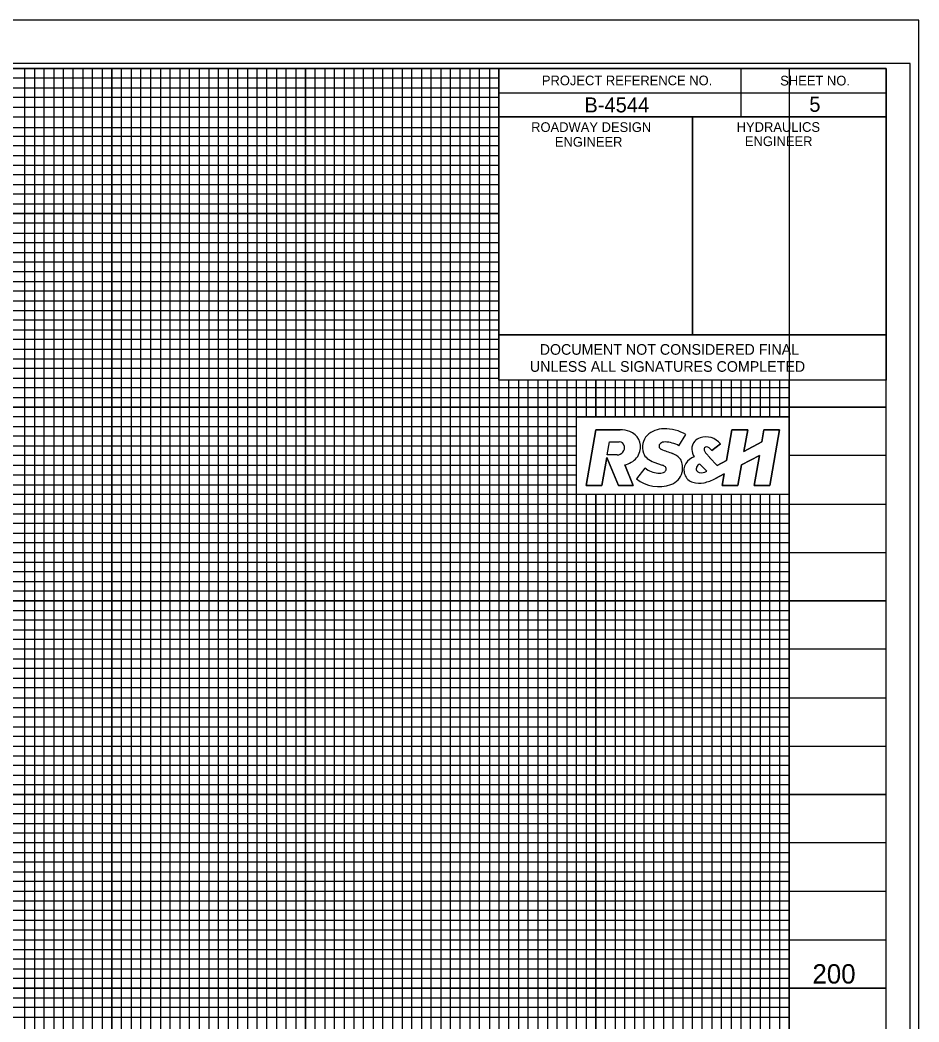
# Model space of a CAD drawing. Extents: x 1728093 to 1729777, y 538013 to 539113.
# Drawn here: x 1729312 to 1729777, y 538595 to 539113 of the extents above; entities that cross this region are included whole.
import ezdxf

# ---------------------------------------------------------------- set-up
doc = ezdxf.new("R2010")
doc.units = 0
for name, color, linetype in [('Exist Vertical Profile Vertical Axis Label', 7, 'Continuous'), ('Prop DSN Text', 7, 'Continuous'), ('Scratch_Level_0', 7, 'Continuous'), ('Sheet Cutting Line CELL', 7, 'Continuous'), ('Sheet Data Field CELL', 7, 'Continuous'), ('Sheet DOT Grid CELL', 7, 'Continuous'), ('Sheet Plot Border Inside CELL', 7, 'Continuous'), ('Sheet Plot Border Outside CELL', 7, 'Continuous'), ('Sheet Profile CELL', 7, 'Continuous'), ('Sheet Profile Grid Major CELL', 7, 'Continuous'), ('Sheet Profile Grid Middle CELL', 7, 'Continuous'), ('Sheet Profile Grid Minor CELL', 7, 'Continuous'), ('Sheet Sticker Exception Certification CELL', 7, 'Continuous'), ('Sheet Sticker Incomplete CELL', 7, 'Continuous')]:
    doc.layers.add(name, color=color, linetype=linetype)

msp = doc.modelspace()

# ---------------------------------------------------------------- linework, layer by layer
at = {"layer": 'Prop DSN Text'}
for p, q in [((1729599.88, 538907.97), (1729709.89, 538907.99)), ((1729599.88, 538867.97), (1729599.88, 538907.97)), ((1729709.89, 538907.99), (1729709.9, 538867.99)), ((1729709.9, 538867.99), (1729599.88, 538867.97))]:
    msp.add_line(p, q, dxfattribs=at)
at = {"layer": 'Scratch_Level_0'}
msp.add_lwpolyline([(1728309.89, 539087.97), (1729709.89, 539087.97), (1729709.89, 538062.97), (1728309.89, 538062.97)], close=True, dxfattribs=at)
at = {"layer": 'Sheet Cutting Line CELL'}
msp.add_line((1729776.89, 539112.97), (1728092.89, 539112.97), dxfattribs=at)
at = {"layer": 'Sheet DOT Grid CELL'}
for p, q in [((1729359.89, 539087.97), (1729359.89, 538062.97)), ((1729409.89, 539087.97), (1729409.89, 538062.97)), ((1729459.89, 539087.97), (1729459.89, 538062.97)), ((1729509.89, 539087.97), (1729509.89, 538062.97)), ((1728259.89, 539062.97), (1729559.84, 539062.97)), ((1728259.89, 539012.97), (1729559.84, 539012.97)), ((1728259.89, 538962.97), (1729559.84, 538962.97)), ((1729559.89, 538062.97), (1729559.89, 538950.42)), ((1729609.89, 538907.97), (1729609.89, 538926.92)), ((1729659.89, 538907.98), (1729659.89, 538926.92)), ((1729709.89, 538062.97), (1729709.89, 538926.92)), ((1728259.89, 538912.97), (1729759.89, 538912.97)), ((1729609.89, 538062.97), (1729609.89, 538867.97)), ((1729659.89, 538062.97), (1729659.89, 538867.98)), ((1728259.89, 538862.97), (1729759.89, 538862.97)), ((1728259.89, 538812.97), (1729759.89, 538812.97)), ((1728259.89, 538762.97), (1729759.89, 538762.97)), ((1728259.89, 538712.97), (1729759.89, 538712.97)), ((1728259.89, 538612.97), (1729759.89, 538612.97))]:
    msp.add_line(p, q, dxfattribs=at)
at = {"layer": 'Sheet Plot Border Inside CELL'}
msp.add_lwpolyline([(1729772.39, 539090.52), (1728105.89, 539090.52), (1728105.89, 538035.42), (1729772.39, 538035.42)], close=True, dxfattribs=at)
at = {"layer": 'Sheet Plot Border Outside CELL'}
msp.add_lwpolyline([(1729776.89, 539112.97), (1728092.89, 539112.97), (1728092.89, 538012.97), (1729776.89, 538012.97)], close=True, dxfattribs=at)
at = {"layer": 'Sheet Profile CELL'}
for p, q in [((1729684.89, 539087.92), (1729684.89, 539062.92)), ((1729559.84, 539075.42), (1729759.89, 539075.42)), ((1729659.89, 539062.92), (1729659.89, 538950.47))]:
    msp.add_line(p, q, dxfattribs=at)
for points in [[(1729759.89, 539087.97), (1728259.89, 539087.97), (1728259.89, 538037.97), (1729759.89, 538037.97)], [(1729559.84, 539087.97), (1729759.89, 539087.97), (1729759.89, 539062.92), (1729559.84, 539062.92)], [(1729559.84, 539062.92), (1729659.89, 539062.92), (1729659.89, 538950.42), (1729559.84, 538950.42)], [(1729659.89, 539062.92), (1729759.89, 539062.92), (1729759.89, 538950.42), (1729659.89, 538950.42)]]:
    msp.add_lwpolyline(points, close=True, dxfattribs=at)
at = {"layer": 'Sheet Profile Grid Major CELL'}
for points in [[(1729359.89, 538062.97), (1729359.89, 539087.97), (1729409.89, 539087.97), (1729409.89, 538062.97)], [(1729459.89, 538062.97), (1729459.89, 539087.97), (1729509.89, 539087.97), (1729509.89, 538062.97)], [(1729559.89, 538062.97), (1729559.89, 539087.97), (1729586.19, 539087.97)], [(1729559.84, 539012.97), (1728259.99, 539012.97), (1728259.99, 539062.92), (1729559.84, 539062.92)], [(1729759.89, 538912.97), (1728259.89, 538912.97), (1728259.89, 538962.97), (1729559.84, 538962.97)], [(1729609.89, 538926.92), (1729609.89, 538907.97)], [(1729659.89, 538907.98), (1729659.89, 538926.92)], [(1729709.89, 538926.92), (1729709.89, 538062.97), (1729759.89, 538062.97)], [(1729609.89, 538867.97), (1729609.89, 538062.97), (1729659.89, 538062.97), (1729659.89, 538867.98)], [(1729759.89, 538812.97), (1728259.89, 538812.97), (1728259.89, 538862.97), (1729759.89, 538862.97)], [(1729759.89, 538712.97), (1728259.89, 538712.97), (1728259.89, 538762.97), (1729759.89, 538762.97)], [(1729759.89, 538612.97), (1728259.89, 538612.97), (1728259.89, 538662.97), (1729759.89, 538662.97)]]:
    msp.add_lwpolyline(points, dxfattribs=at)
at = {"layer": 'Sheet Profile Grid Middle CELL'}
for points in [[(1729334.89, 538062.97), (1729334.89, 539087.97), (1729384.89, 539087.97), (1729384.89, 538062.97)], [(1729434.89, 538062.97), (1729434.89, 539087.97), (1729484.89, 539087.97), (1729484.89, 538062.97)], [(1729534.89, 538062.97), (1729534.89, 539087.97)], [(1728259.89, 539037.97), (1729559.84, 539037.97)], [(1729559.84, 538987.97), (1728259.89, 538987.97), (1728259.89, 538937.92), (1729559.84, 538937.92)], [(1729584.89, 538926.92), (1729584.89, 538062.97), (1729634.89, 538062.97), (1729634.89, 538867.98)], [(1729634.89, 538907.98), (1729634.89, 538926.92)], [(1729684.89, 538926.92), (1729684.89, 538907.98)], [(1729599.88, 538887.97), (1728259.89, 538887.97), (1728259.89, 538837.97), (1729759.89, 538837.97)], [(1729759.89, 538887.97), (1729709.89, 538887.97)], [(1729684.89, 538867.98), (1729684.89, 538062.97)], [(1729759.89, 538787.97), (1728259.89, 538787.97), (1728259.89, 538737.97), (1729759.89, 538737.97)], [(1729759.89, 538687.97), (1728259.89, 538687.97), (1728259.89, 538637.97), (1729759.89, 538637.97)]]:
    msp.add_lwpolyline(points, dxfattribs=at)
at = {"layer": 'Sheet Profile Grid Minor CELL'}
for p, q in [((1729709.89, 538922.97), (1728309.89, 538922.97)), ((1728309.89, 538917.97), (1729709.89, 538917.97)), ((1729709.89, 538907.97), (1728309.89, 538907.97)), ((1728309.89, 538902.97), (1729599.88, 538902.97)), ((1729599.88, 538882.97), (1728309.89, 538882.97)), ((1729709.89, 538852.97), (1728309.89, 538852.97)), ((1728309.89, 538847.97), (1729709.89, 538847.97))]:
    msp.add_line(p, q, dxfattribs=at)
for points in [[(1729314.89, 538062.97), (1729314.89, 539087.97), (1729319.89, 539087.97), (1729319.89, 538062.97)], [(1729324.89, 538062.97), (1729324.89, 539087.97), (1729329.89, 539087.97), (1729329.89, 538062.97)], [(1729339.89, 538062.97), (1729339.89, 539087.97), (1729344.89, 539087.97), (1729344.89, 538062.97)], [(1729349.89, 538062.97), (1729349.89, 539087.97), (1729354.89, 539087.97), (1729354.89, 538062.97)], [(1729364.89, 538062.97), (1729364.89, 539087.97), (1729369.89, 539087.97), (1729369.89, 538062.97)], [(1729374.89, 538062.97), (1729374.89, 539087.97), (1729379.89, 539087.97), (1729379.89, 538062.97)], [(1729389.89, 538062.97), (1729389.89, 539087.97), (1729394.89, 539087.97), (1729394.89, 538062.97)], [(1729399.89, 538062.97), (1729399.89, 539087.97), (1729404.89, 539087.97), (1729404.89, 538062.97)], [(1729414.89, 538062.97), (1729414.89, 539087.97), (1729419.89, 539087.97), (1729419.89, 538062.97)], [(1729424.89, 538062.97), (1729424.89, 539087.97), (1729429.89, 539087.97), (1729429.89, 538062.97)], [(1729439.89, 538062.97), (1729439.89, 539087.97), (1729444.89, 539087.97), (1729444.89, 538062.97)], [(1729449.89, 538062.97), (1729449.89, 539087.97), (1729454.89, 539087.97), (1729454.89, 538062.97)], [(1729464.89, 538062.97), (1729464.89, 539087.97), (1729469.89, 539087.97), (1729469.89, 538062.97)], [(1729474.89, 538062.97), (1729474.89, 539087.97), (1729479.89, 539087.97), (1729479.89, 538062.97)], [(1729489.89, 538062.97), (1729489.89, 539087.97), (1729494.89, 539087.97), (1729494.89, 538062.97)], [(1729499.89, 538062.97), (1729499.89, 539087.97), (1729504.89, 539087.97), (1729504.89, 538062.97)], [(1729514.89, 538062.97), (1729514.89, 539087.97), (1729519.89, 539087.97), (1729519.89, 538062.97)], [(1729524.89, 538062.97), (1729524.89, 539087.97), (1729529.89, 539087.97), (1729529.89, 538062.97)], [(1729539.89, 538062.97), (1729539.89, 539087.97), (1729544.89, 539087.97), (1729544.89, 538062.97)], [(1729549.89, 538062.97), (1729549.89, 539087.97), (1729554.89, 539087.97), (1729554.89, 538062.97)], [(1729559.84, 539082.97), (1728309.89, 539082.97), (1728309.89, 539077.97), (1729559.84, 539077.97)], [(1729559.84, 539072.97), (1728309.89, 539072.97), (1728309.89, 539067.97), (1729559.84, 539067.97)], [(1729559.84, 539057.22), (1728310.89, 539057.22), (1728310.89, 539052.97), (1729559.84, 539052.97)], [(1729559.84, 539047.97), (1728309.89, 539047.97), (1728309.89, 539042.97), (1729559.84, 539042.97)], [(1729559.84, 539032.97), (1728309.89, 539032.97), (1728309.89, 539027.97), (1729559.84, 539027.97)], [(1729559.84, 539022.97), (1728309.89, 539022.97), (1728309.89, 539017.97), (1729559.84, 539017.97)], [(1729559.84, 539007.97), (1728309.89, 539007.97), (1728309.89, 539002.97), (1729559.84, 539002.97)], [(1729559.84, 538997.97), (1728309.89, 538997.97), (1728309.89, 538992.97), (1729559.84, 538992.97)], [(1729559.84, 538982.97), (1728309.89, 538982.97), (1728309.89, 538977.97), (1729559.84, 538977.97)], [(1729559.84, 538972.97), (1728309.89, 538972.97), (1728309.89, 538967.97), (1729559.84, 538967.97)], [(1729559.84, 538957.97), (1728309.89, 538957.97), (1728309.89, 538952.97), (1729559.84, 538952.97)], [(1729559.84, 538947.97), (1728309.89, 538947.97), (1728309.89, 538947.97), (1728309.89, 538927.97), (1729559.84, 538927.97)], [(1728309.89, 538942.97), (1729559.84, 538942.97)], [(1729559.84, 538932.97), (1728309.89, 538932.97)], [(1729564.89, 538062.97), (1729564.89, 538926.92)], [(1729569.89, 538926.92), (1729569.89, 538062.97), (1729574.89, 538062.97), (1729574.89, 538926.92)], [(1729579.89, 538926.92), (1729579.89, 538062.97), (1729589.89, 538062.97), (1729589.89, 538926.92)], [(1729594.89, 538926.92), (1729594.89, 538062.97), (1729599.89, 538062.97), (1729599.89, 538926.92)], [(1729604.89, 538926.92), (1729604.89, 538907.97)], [(1729614.89, 538907.97), (1729614.89, 538926.92)], [(1729619.89, 538926.92), (1729619.89, 538907.97)], [(1729624.89, 538907.98), (1729624.89, 538926.92)], [(1729629.89, 538926.92), (1729629.89, 538907.98)], [(1729639.89, 538907.98), (1729639.89, 538926.92)], [(1729644.89, 538926.92), (1729644.89, 538907.98)], [(1729649.89, 538907.98), (1729649.89, 538926.92)], [(1729654.89, 538926.92), (1729654.89, 538907.98)], [(1729664.89, 538907.98), (1729664.89, 538926.92)], [(1729669.89, 538926.92), (1729669.89, 538907.98)], [(1729674.89, 538907.98), (1729674.89, 538926.92)], [(1729679.89, 538926.92), (1729679.89, 538907.98)], [(1729689.89, 538907.98), (1729689.89, 538926.92)], [(1729694.89, 538926.92), (1729694.89, 538907.98)], [(1729699.89, 538907.98), (1729699.89, 538926.92)], [(1729704.89, 538926.92), (1729704.89, 538907.99)], [(1729599.88, 538897.97), (1728309.89, 538897.97), (1728309.89, 538892.97), (1729599.88, 538892.97)], [(1729599.88, 538877.97), (1728309.89, 538877.97), (1728309.89, 538872.97), (1729599.88, 538872.97)], [(1729709.89, 538867.97), (1728309.89, 538867.97)], [(1729604.89, 538867.97), (1729604.89, 538062.97), (1729614.89, 538062.97), (1729614.89, 538867.97)], [(1729619.89, 538867.97), (1729619.89, 538062.97), (1729624.89, 538062.97), (1729624.89, 538867.98)], [(1729629.89, 538867.98), (1729629.89, 538062.97), (1729639.89, 538062.97), (1729639.89, 538867.98)], [(1729644.89, 538062.97), (1729649.89, 538062.97), (1729649.89, 538867.98)], [(1729644.89, 538867.98), (1729644.89, 538062.97)], [(1729654.89, 538867.98), (1729654.89, 538062.97), (1729664.89, 538062.97), (1729664.89, 538867.98)], [(1729669.89, 538867.98), (1729669.89, 538062.97), (1729674.89, 538062.97), (1729674.89, 538867.98)], [(1729679.89, 538867.98), (1729679.89, 538062.97), (1729689.89, 538062.97), (1729689.89, 538867.98)], [(1729694.89, 538867.98), (1729694.89, 538062.97), (1729699.89, 538062.97), (1729699.89, 538867.98)], [(1729704.89, 538867.99), (1729704.89, 538062.97), (1729714.89, 538062.97)], [(1728309.89, 538857.97), (1729709.89, 538857.97)], [(1729709.89, 538842.97), (1728309.89, 538842.97), (1728309.89, 538832.97), (1729709.89, 538832.97)], [(1729709.89, 538827.97), (1728309.89, 538827.97), (1728309.89, 538822.97), (1729709.89, 538822.97)], [(1729709.89, 538817.97), (1728309.89, 538817.97), (1728309.89, 538807.97), (1729709.89, 538807.97)], [(1729709.89, 538802.97), (1728309.89, 538802.97), (1728309.89, 538797.97), (1729709.89, 538797.97)], [(1729709.89, 538792.97), (1728309.89, 538792.97), (1728309.89, 538782.97), (1729709.89, 538782.97)], [(1729709.89, 538777.97), (1728309.89, 538777.97), (1728309.89, 538772.97), (1729709.89, 538772.97)], [(1729709.89, 538767.97), (1728309.89, 538767.97), (1728309.89, 538757.97), (1729709.89, 538757.97)], [(1729709.89, 538752.97), (1728309.89, 538752.97), (1728309.89, 538747.97), (1729709.89, 538747.97)], [(1729709.89, 538742.97), (1728309.89, 538742.97), (1728309.89, 538732.97), (1729709.89, 538732.97)], [(1729709.89, 538727.97), (1728309.89, 538727.97), (1728309.89, 538722.97), (1729709.89, 538722.97)], [(1729709.89, 538717.97), (1728309.89, 538717.97), (1728309.89, 538707.97), (1729709.89, 538707.97)], [(1729709.89, 538702.97), (1728309.89, 538702.97), (1728309.89, 538697.97), (1729709.89, 538697.97)], [(1729709.89, 538692.97), (1728309.89, 538692.97), (1728309.89, 538682.97), (1729709.89, 538682.97)], [(1729709.89, 538677.97), (1728309.89, 538677.97), (1728309.89, 538672.97), (1729709.89, 538672.97)], [(1729709.89, 538667.97), (1728309.89, 538667.97), (1728309.89, 538657.97), (1729709.89, 538657.97)], [(1729709.89, 538652.97), (1728309.89, 538652.97), (1728309.89, 538647.97), (1729709.89, 538647.97)], [(1729709.89, 538642.97), (1728309.89, 538642.97), (1728309.89, 538632.97), (1729709.89, 538632.97)], [(1729709.89, 538627.97), (1728309.89, 538627.97), (1728309.89, 538622.97), (1729709.89, 538622.97)], [(1729709.89, 538617.97), (1728309.89, 538617.97), (1728309.89, 538607.97), (1729709.89, 538607.97)], [(1729709.89, 538602.97), (1728309.89, 538602.97), (1728309.89, 538597.97), (1729709.89, 538597.97)]]:
    msp.add_lwpolyline(points, dxfattribs=at)
at = {"layer": 'Sheet Sticker Exception Certification CELL'}
for p, q in [((1729559.84, 538926.92), (1729559.84, 538950.42)), ((1729559.84, 538950.42), (1729759.88, 538950.42)), ((1729759.88, 538950.41), (1729759.88, 538926.91)), ((1729759.88, 538926.92), (1729559.84, 538926.92))]:
    msp.add_line(p, q, dxfattribs=at)
at = {"layer": 'Sheet Sticker Incomplete CELL'}
for p, q in [((1729604.91, 538872.54), (1729609.99, 538901.35)), ((1729609.99, 538901.35), (1729604.91, 538872.54)), ((1729609.99, 538901.35), (1729622.49, 538901.35)), ((1729622.49, 538901.35), (1729609.99, 538901.35)), ((1729652.87, 538893.05), (1729656.49, 538898.85)), ((1729677.52, 538885.47), (1729680.28, 538901.35)), ((1729680.28, 538901.35), (1729677.52, 538885.47)), ((1729680.28, 538901.35), (1729688.4, 538901.35)), ((1729688.4, 538901.35), (1729680.28, 538901.35)), ((1729688.4, 538901.35), (1729686.42, 538890.14)), ((1729686.42, 538890.14), (1729688.4, 538901.35)), ((1729695.69, 538895.1), (1729696.81, 538901.33)), ((1729696.81, 538901.33), (1729695.69, 538895.1)), ((1729696.81, 538901.33), (1729704.88, 538901.33)), ((1729704.88, 538901.33), (1729696.81, 538901.33)), ((1729704.88, 538901.33), (1729699.85, 538872.5)), ((1729699.85, 538872.5), (1729704.88, 538901.33)), ((1729615.81, 538888.38), (1729616.99, 538895.17)), ((1729615.81, 538888.38), (1729616.99, 538895.17)), ((1729616.99, 538895.17), (1729622.05, 538895.17)), ((1729616.99, 538895.17), (1729622.05, 538895.17)), ((1729674.27, 538894.07), (1729669.89, 538890.71)), ((1729669.89, 538890.71), (1729674.27, 538894.07)), ((1729686.42, 538890.14), (1729695.69, 538895.1)), ((1729695.69, 538895.1), (1729686.42, 538890.14)), ((1729620.88, 538888.38), (1729615.81, 538888.38)), ((1729620.88, 538888.38), (1729615.81, 538888.38)), ((1729666.92, 538889.15), (1729668.79, 538887)), ((1729668.79, 538887), (1729666.92, 538889.15)), ((1729615.56, 538887.07), (1729612.97, 538872.54)), ((1729612.97, 538872.54), (1729615.56, 538887.07)), ((1729621.58, 538872.49), (1729615.56, 538887.07)), ((1729615.56, 538887.07), (1729621.58, 538872.49)), ((1729624.88, 538883.22), (1729629.25, 538872.49)), ((1729629.25, 538872.49), (1729624.88, 538883.22)), ((1729639.84, 538884.63), (1729644.27, 538883.12)), ((1729667.23, 538879.95), (1729663.65, 538883.66)), ((1729663.65, 538883.66), (1729667.23, 538879.95)), ((1729668.74, 538887.07), (1729672.65, 538882.93)), ((1729668.79, 538887), (1729668.74, 538887.07)), ((1729672.65, 538882.93), (1729668.74, 538887.07)), ((1729668.74, 538887.07), (1729668.79, 538887)), ((1729672.65, 538882.93), (1729677.52, 538885.47)), ((1729677.52, 538885.47), (1729672.65, 538882.93)), ((1729685.18, 538883.26), (1729683.32, 538872.5)), ((1729683.32, 538872.5), (1729685.18, 538883.26)), ((1729694.48, 538888.12), (1729685.18, 538883.26)), ((1729685.18, 538883.26), (1729694.48, 538888.12)), ((1729691.66, 538872.5), (1729694.48, 538888.12)), ((1729694.48, 538888.12), (1729691.66, 538872.5)), ((1729635.17, 538881.53), (1729630.86, 538875.93)), ((1729636.15, 538880.92), (1729635.17, 538881.53)), ((1729676.25, 538878.53), (1729671.74, 538876.15)), ((1729671.74, 538876.15), (1729676.25, 538878.53)), ((1729675.14, 538872.5), (1729676.25, 538878.53)), ((1729676.25, 538878.53), (1729675.14, 538872.5)), ((1729612.97, 538872.54), (1729604.91, 538872.54)), ((1729604.91, 538872.54), (1729612.97, 538872.54)), ((1729629.25, 538872.49), (1729621.58, 538872.49)), ((1729621.58, 538872.49), (1729629.25, 538872.49)), ((1729683.32, 538872.5), (1729675.14, 538872.5)), ((1729675.14, 538872.5), (1729683.32, 538872.5)), ((1729699.85, 538872.5), (1729691.66, 538872.5)), ((1729691.66, 538872.5), (1729699.85, 538872.5))]:
    msp.add_line(p, q, dxfattribs=at)
for centre, radius, start, end in [((1729622.49, 538887.02), 14.33, 69.6948, 90), ((1729622.49, 538887.02), 14.33, 69.6948, 90), ((1729624.51, 538892.47), 8.51, 344.0221, 69.6948), ((1729624.51, 538892.47), 8.51, 344.0221, 69.6948), ((1729644.12, 538890.82), 10.81, 110.0514, 134.9819), ((1729645.33, 538887.51), 14.33, 91.1674, 110.0517), ((1729645.48, 538880.09), 21.75, 59.5747, 91.1674), ((1729622.05, 538892.51), 2.66, 12.5709, 90), ((1729622.05, 538892.51), 2.66, 12.5709, 90), ((1729642.59, 538892.34), 8.65, 134.9819, 200.374), ((1729644.3, 538892.88), 1.75, 124.8691, 249.8559), ((1729645.62, 538890.98), 4.05, 88.9947, 124.8691), ((1729645.43, 538880.09), 14.95, 60.1495, 88.9947), ((1729665.09, 538891.57), 5.61, 136.157, 184.3284), ((1729665.09, 538891.57), 5.61, 136.157, 184.3284), ((1729665.91, 538890.78), 6.74, 108.3191, 136.157), ((1729665.91, 538890.78), 6.74, 108.3191, 136.157), ((1729666.8, 538888.1), 9.57, 38.6078, 108.3191), ((1729666.8, 538888.1), 9.57, 38.6078, 108.3191), ((1729620.88, 538892.24), 3.87, 270, 12.5711), ((1729620.88, 538892.24), 3.87, 270, 12.5711), ((1729623.9, 538892.64), 9.14, 297.8379, 344.0221), ((1729623.9, 538892.64), 9.14, 297.8379, 344.0221), ((1729640.75, 538891.66), 6.69, 200.374, 230.3377), ((1729879.92, 539535.21), 685.93, 249.8559, 250.3798), ((1729646.7, 538880.99), 8.61, 40.1181, 70.3798), ((1729668.03, 538891.79), 8.56, 184.3284, 211.1216), ((1729668.03, 538891.79), 8.56, 184.3284, 211.1216), ((1729667.3, 538891.12), 1.4, 186.4006, 205.4834), ((1729667.3, 538891.12), 1.4, 186.4006, 205.4834), ((1729671.46, 538893.1), 6.01, 205.4834, 221.0188), ((1729671.46, 538893.1), 6.01, 205.4834, 221.0188), ((1729619.82, 538900.37), 17.89, 286.4254, 297.8379), ((1729619.82, 538900.37), 17.89, 286.4254, 297.8379), ((1729643.3, 538894.73), 10.67, 230.3377, 251.1129), ((1729642.77, 538878.72), 4.64, 52.7017, 70.6731), ((1729649.16, 538883.07), 5.4, 15.068, 40.1181), ((1729643.16, 538881.45), 11.62, 360, 15.068), ((1729661.96, 538880.46), 6.52, 147.3625, 253.3619), ((1729661.96, 538880.46), 6.52, 147.3625, 253.3619), ((1729663.6, 538879.41), 8.47, 110.004, 147.3628), ((1729663.6, 538879.41), 8.47, 110.004, 147.3625), ((1729664.98, 538880.61), 3.32, 113.6387, 153.7792), ((1729664.98, 538880.61), 3.32, 113.6387, 153.7792), ((1729643.37, 538892.59), 13.72, 238.2427, 267.7951), ((1729643.01, 538883.28), 4.4, 267.7951, 304.7166), ((1729644.55, 538881.06), 1.7, 304.7166, 52.7017), ((1729645.83, 538881.52), 8.95, 288.9071, 346.2053), ((1729646.11, 538881.45), 8.67, 346.2053, 0), ((1729663.76, 538881.21), 1.96, 153.7792, 258.3171), ((1729663.76, 538881.21), 1.96, 153.7792, 258.3171), ((1729664.46, 538884.56), 5.38, 258.3171, 300.9583), ((1729664.46, 538884.56), 5.38, 258.3171, 300.9583), ((1729642.5, 538891.25), 19.24, 232.7848, 288.9071), ((1729663.39, 538885.24), 11.51, 253.3619, 282.1538), ((1729663.39, 538885.24), 11.51, 253.3619, 282.1538), ((1729660.94, 538896.61), 23.14, 282.1538, 297.8191), ((1729660.94, 538896.61), 23.14, 282.1538, 297.8191)]:
    msp.add_arc(centre, radius, start, end, dxfattribs=at)
msp.add_ellipse((1729668.52, 538889.55), major_axis=(2.24, -2.68), ratio=0.514434, start_param=1.570796, end_param=3.802211, dxfattribs=at)
msp.add_ellipse((1729668.52, 538889.55), major_axis=(2.24, -2.68), ratio=0.514434, start_param=1.570796, end_param=3.802211, dxfattribs=at)

# ---------------------------------------------------------------- texts
at = {"layer": 'Exist Vertical Profile Vertical Axis Label'}
msp.add_text('200', height=10, dxfattribs=at).set_placement((1729721.83, 538615.31))
at = {"layer": 'Sheet Data Field CELL'}
for s, p in [('B-4544', (1729604.03, 539065.27)), ('5', (1729720.23, 539065.57))]:
    msp.add_text(s, height=7.75, dxfattribs=at).set_placement(p)
at = {"layer": 'Sheet Profile CELL'}
for s, height, p in [('PROJECT REFERENCE NO.', 5.0001, (1729582.04, 539079.27)), ('SHEET NO.', 5, (1729705.19, 539079.17)), ('ROADWAY DESIGN', 5.0001, (1729576.49, 539055.17)), ('HYDRAULICS', 5, (1729682.69, 539055.22)), ('ENGINEER', 5, (1729588.74, 539047.57)), ('ENGINEER', 5, (1729686.94, 539047.87))]:
    msp.add_text(s, height=height, dxfattribs=at).set_placement(p)
at = {"layer": 'Sheet Sticker Exception Certification CELL'}
for s, p in [('DOCUMENT NOT CONSIDERED FINAL', (1729580.91, 538940.08)), ('UNLESS ALL SIGNATURES COMPLETED', (1729575.84, 538931.28))]:
    msp.add_text(s, height=5.5, dxfattribs=at).set_placement(p)

doc.saveas('drawing.dxf')
